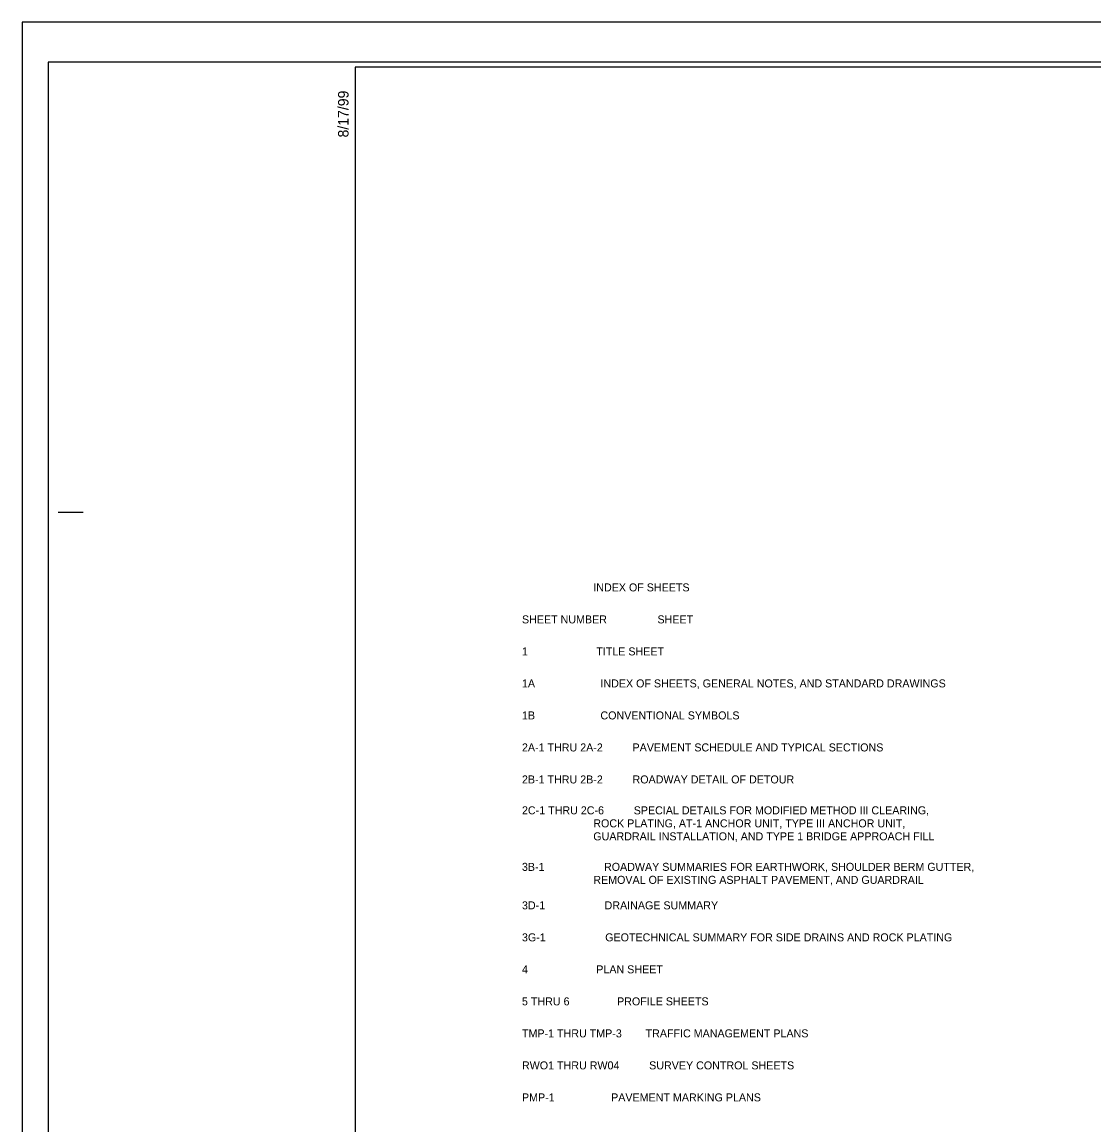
# Model space of a CAD drawing. Extents: x 1983800 to 2121016, y 627229 to 697309.
# Drawn here: x 1983800 to 2018104, y 662023 to 697309 of the extents above; entities that cross this region are included whole.
import ezdxf

# ---------------------------------------------------------------- set-up
doc = ezdxf.new("R2010")
doc.units = 0
for name, color, linetype in [('Sheet Cutting Line CELL', 7, 'Continuous'), ('Sheet Data Text CELL', 7, 'Continuous'), ('Sheet Plan CELL', 7, 'Continuous'), ('Sheet Plot Border Inside CELL', 7, 'Continuous'), ('Sheet Plot Border Outside CELL', 7, 'Continuous')]:
    doc.layers.add(name, color=color, linetype=linetype)

msp = doc.modelspace()

# ---------------------------------------------------------------- linework, layer by layer
at = {"layer": 'Sheet Cutting Line CELL'}
for p, q in [((2091544, 697309), (1983800, 697309)), ((1983800, 697309), (1983800, 627229))]:
    msp.add_line(p, q, dxfattribs=at)
at = {"layer": 'Sheet Plan CELL'}
for p, q in [((1994456, 695869), (1994456, 695869)), ((1984952, 681629), (1985752, 681629))]:
    msp.add_line(p, q, dxfattribs=at)
msp.add_lwpolyline([(2090456, 695869), (1994456, 695869), (1994456, 628669), (2090456, 628669)], close=True, dxfattribs=at)
at = {"layer": 'Sheet Plot Border Inside CELL'}
msp.add_lwpolyline([(1984632, 628509), (2091256, 628509), (2091256, 696029), (1984632, 696029)], close=True, dxfattribs=at)
at = {"layer": 'Sheet Plot Border Outside CELL'}
msp.add_lwpolyline([(1983800, 627229), (2091544, 627229), (2091544, 697309), (1983800, 697309)], close=True, dxfattribs=at)

# ---------------------------------------------------------------- texts
at = {"layer": 'Sheet Data Text CELL'}
for s, p in [('                        INDEX OF SHEETS ', (1999799, 679093)), ('SHEET NUMBER                 SHEET   ', (1999799, 678069)), ('1                       TITLE SHEET', (1999799, 677045)), ('1A                      INDEX OF SHEETS, GENERAL NOTES, AND STANDARD DRAWINGS', (1999799, 676021)), ('1B                      CONVENTIONAL SYMBOLS ', (1999799, 674997)), ('2A-1 THRU 2A-2          PAVEMENT SCHEDULE AND TYPICAL SECTIONS', (1999799, 673973)), ('2B-1 THRU 2B-2          ROADWAY DETAIL OF DETOUR', (1999799, 672949)), ('2C-1 THRU 2C-6          SPECIAL DETAILS FOR MODIFIED METHOD III CLEARING,', (1999799, 671960)), ('                        ROCK PLATING, AT-1 ANCHOR UNIT, TYPE III ANCHOR UNIT,', (1999799, 671544)), ('                        GUARDRAIL INSTALLATION, AND TYPE 1 BRIDGE APPROACH FILL', (1999799, 671128)), ('3B-1                    ROADWAY SUMMARIES FOR EARTHWORK, SHOULDER BERM GUTTER,', (1999799, 670152)), ('                        REMOVAL OF EXISTING ASPHALT PAVEMENT, AND GUARDRAIL', (1999799, 669736)), ('3D-1                    DRAINAGE SUMMARY', (1999799, 668920)), ('3G-1                    GEOTECHNICAL SUMMARY FOR SIDE DRAINS AND ROCK PLATING', (1999799, 667896)), ('4                       PLAN SHEET', (1999799, 666872)), ('5 THRU 6                PROFILE SHEETS', (1999799, 665848)), ('TMP-1 THRU TMP-3        TRAFFIC MANAGEMENT PLANS', (1999799, 664824)), ('RWO1 THRU RW04          SURVEY CONTROL SHEETS', (1999799, 663800)), ('PMP-1                   PAVEMENT MARKING PLANS', (1999799, 662776))]:
    msp.add_text(s, height=256, dxfattribs=at).set_placement(p)
at = {"layer": 'Sheet Plan CELL'}
msp.add_text('8/17/99', height=336, rotation=90, dxfattribs=at).set_placement((1994248, 693616))

doc.saveas('drawing.dxf')
